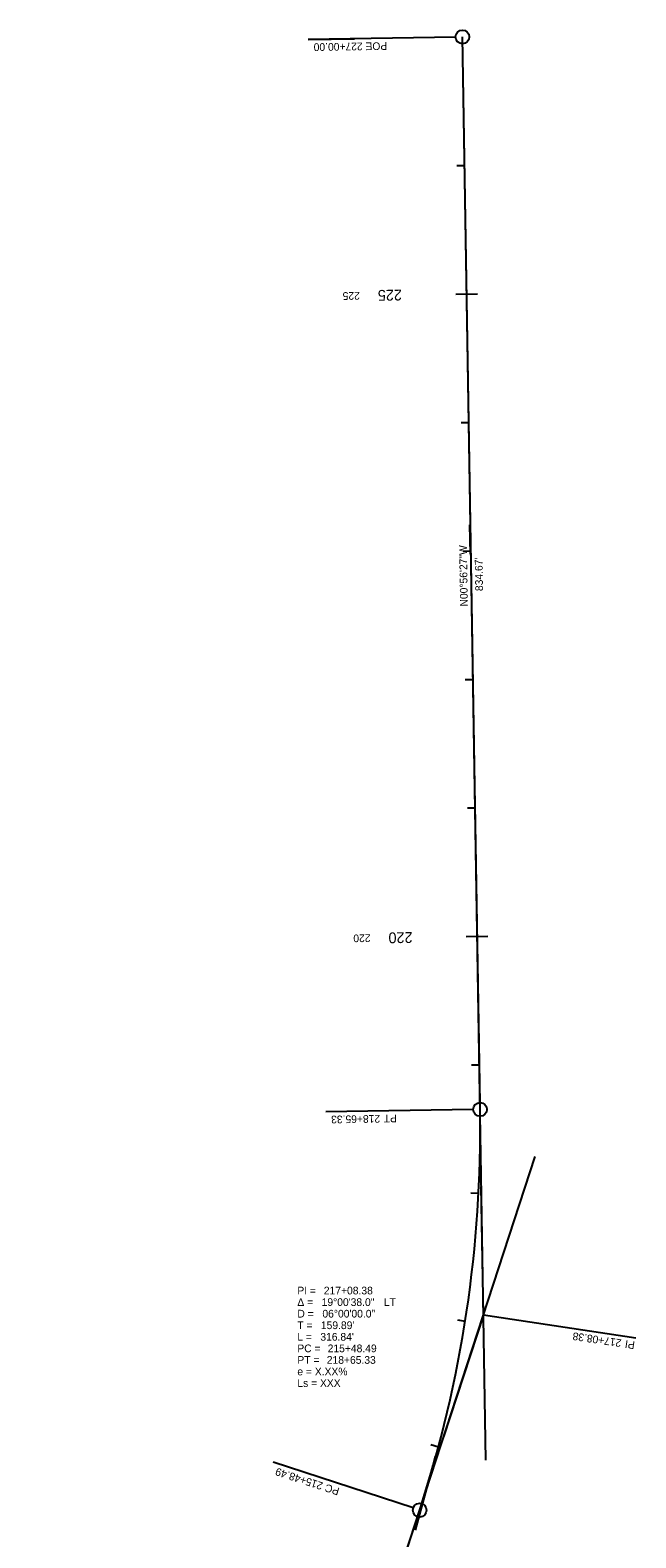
# Model space of a CAD drawing. Extents: x 1803080 to 1803655, y 572742 to 575010.
# Drawn here: x 1803184 to 1803655, y 573837 to 575010 of the extents above; entities that cross this region are included whole.
import ezdxf

# ---------------------------------------------------------------- set-up
doc = ezdxf.new("R2010")
doc.units = 0
for name, color, linetype in [('DSN_DRFT_Common-Annotations', 7, 'Continuous'), ('DSN_DRFT_DNC', 7, 'Continuous'), ('DSN_RDWY_Alignment', 7, 'Continuous'), ('DSN_RDWY_Alignment Annotation', 7, 'Continuous')]:
    doc.layers.add(name, color=color, linetype=linetype)

msp = doc.modelspace()

# ---------------------------------------------------------------- linework, layer by layer
at = {"layer": 'DSN_DRFT_DNC'}
for p, q in [((1803538.6, 573897.2), (1803520.5, 575004.9)), ((1803525.9, 574625.1), (1803526.4, 574602.6)), ((1803530.1, 574407.6), (1803533.9, 574175.2)), ((1803184, 572929.3), (1803577, 574133.6)), ((1803497.7, 573893.5), (1803499.6, 573900.7)), ((1803484, 573842.8), (1803497.7, 573893.5))]:
    msp.add_line(p, q, dxfattribs=at)
at = {"layer": 'DSN_RDWY_Alignment'}
for p, q in [((1803534.2, 574170.3), (1803520.5, 575004.9)), ((1803249, 573128.3), (1803487.2, 573858.4))]:
    msp.add_line(p, q, dxfattribs=at)
msp.add_arc((1802579.4, 574154.6), 954.9, 341.9303, 0.9408, dxfattribs=at)
msp.add_arc((1802579.4, 574154.6), 954.9, 341.9303, 0.9408, dxfattribs=at)
at = {"layer": 'DSN_RDWY_Alignment Annotation'}
for p, q in [((1803515.1, 575004.8), (1803400.5, 575002.9)), ((1803400.5, 575002.9), (1803436.5, 575003.5)), ((1803520.5, 575004.9), (1803520.5, 575004.9)), ((1803516.1, 574904.8), (1803522.1, 574904.9)), ((1803516.1, 574904.8), (1803522.1, 574904.9)), ((1803515.3, 574804.8), (1803532.1, 574805)), ((1803515.3, 574804.8), (1803532.1, 574805)), ((1803519.4, 574704.8), (1803525.4, 574704.9)), ((1803519.4, 574704.8), (1803525.4, 574704.9)), ((1803521, 574604.8), (1803527, 574604.9)), ((1803521, 574604.8), (1803527, 574604.9)), ((1803522.7, 574504.8), (1803528.7, 574504.9)), ((1803522.7, 574504.8), (1803528.7, 574504.9)), ((1803524.3, 574404.9), (1803530.3, 574405)), ((1803524.3, 574404.9), (1803530.3, 574405)), ((1803523.5, 574304.8), (1803540.3, 574305.1)), ((1803523.5, 574304.8), (1803540.3, 574305.1)), ((1803527.6, 574204.9), (1803533.6, 574205)), ((1803527.6, 574204.9), (1803533.6, 574205)), ((1803528.8, 574170.2), (1803414.2, 574168.4)), ((1803414.2, 574168.4), (1803414.2, 574168.4)), ((1803534.2, 574170.3), (1803534.2, 574170.3)), ((1803536.8, 574010.5), (1803535.1, 574110.4)), ((1803527, 574105.3), (1803533, 574105)), ((1803527, 574105.3), (1803533, 574105)), ((1803536.8, 574010.5), (1803505.8, 573915.4)), ((1803516.7, 574006.5), (1803522.6, 574005.6)), ((1803516.7, 574006.5), (1803522.6, 574005.6)), ((1803536.8, 574010.5), (1803655.4, 573992.6)), ((1803655.4, 573992.6), (1803655.4, 573992.6)), ((1803496, 573909.4), (1803501.8, 573907.8)), ((1803496, 573909.4), (1803501.8, 573907.8)), ((1803482.1, 573860.1), (1803373.1, 573895.7)), ((1803373.1, 573895.7), (1803373.1, 573895.7)), ((1803487.2, 573858.4), (1803487.2, 573858.4))]:
    msp.add_line(p, q, dxfattribs=at)
for centre in [(1803520.5, 575004.9), (1803534.2, 574170.3), (1803487.2, 573858.4)]:
    msp.add_circle(centre, 5.34, dxfattribs=at)

# ---------------------------------------------------------------- texts
at = {"layer": 'DSN_DRFT_Common-Annotations'}
msp.add_text("834.67'", height=6, rotation=90.9408, dxfattribs=at).set_placement((1803536.5, 574573.7))
at = {"layer": 'DSN_RDWY_Alignment Annotation'}
for s, height, rotation, p in [('227+00.00', 6, 180.9408, (1803442.8, 575000.6)), ('POE ', 6, 180.9408, (1803461.9, 575000.9)), ('225', 6, 180.9408, (1803440.6, 574806.5)), ('225', 8.4, 180.9408, (1803473.3, 574808.3)), ('N00°56\'27"W', 6, 90.9408, (1803524.7, 574561.7)), ('220', 6, 180.9408, (1803448.9, 574306.6)), ('220', 8.4, 180.9408, (1803481.6, 574308.3)), ('218+65.33', 6, 180.9408, (1803456.4, 574166)), ('PT', 6, 180.9408, (1803469.4, 574166.3)), ('217+08.38', 6, 171.4356, (1803644.5, 573991.2)), ('PI ', 6, 171.4356, (1803655, 573989.6)), ('215+48.49', 6, 161.9303, (1803412.4, 573879.7)), ('PC', 6, 161.9303, (1803425.3, 573875.5))]:
    msp.add_text(s, height=height, rotation=rotation, dxfattribs=at).set_placement(p)
for s, p in [('PI = ', (1803392, 574026.3)), ('217+08.38', (1803412.6, 574026.3)), ('Δ = ', (1803392, 574017.3)), ('D = ', (1803392, 574008.3)), ('19°00\'38.0"', (1803410.9, 574017.3)), ('06°00\'00.0"', (1803411.5, 574008.3)), (' LT', (1803457.1, 574017.3)), ('T = ', (1803392, 573999.3)), ("159.89'", (1803410.3, 573999.3)), ('L = ', (1803392, 573990.3)), ("316.84'", (1803409.9, 573990.3)), ('PC = ', (1803392, 573981.3)), ('PT = ', (1803392, 573972.3)), ('218+65.33', (1803414.9, 573972.3)), ('215+48.49', (1803415.6, 573981.3)), ('e = X.XX%', (1803392, 573963.3)), ('Ls = XXX', (1803392, 573954.3))]:
    msp.add_text(s, height=6, dxfattribs=at).set_placement(p)

doc.saveas('drawing.dxf')
